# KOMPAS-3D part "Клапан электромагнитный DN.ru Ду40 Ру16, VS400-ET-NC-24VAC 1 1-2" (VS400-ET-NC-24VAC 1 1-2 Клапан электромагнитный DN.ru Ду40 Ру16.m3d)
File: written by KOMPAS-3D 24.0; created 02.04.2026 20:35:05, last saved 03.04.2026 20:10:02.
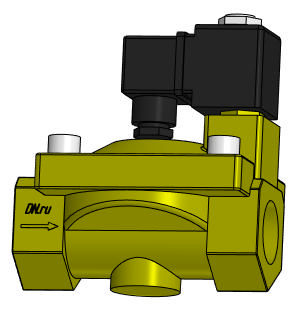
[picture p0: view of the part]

Document properties: Автор: artio; Полное имя файла: C:\Users\artio\OneDrive\Рабочий стол\Клапан электромагнитный DN.ru\VS400-ET-NC\VS400-ET-NC-24VAC 1 1-2 Клапан электромагнитный DN.ru Ду40 Ру16.m3d

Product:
- Body: Тело 1  | qty 1
    Масса: 4.144257
- Part/product: Клапан электромагнитный DN.ru Ду40 Ру16  | designation VS400-ET-NC-24VAC 1 1-2
    Масса: 2.321
    Раздел спецификации: Прочие изделия
    Примечание: D130-05491
    additional columns: ef56311e-7521-43dc-8291-0e6108b3d81d; VS400-ET-NC-220VAC 1 1-2; artio; c; Шероховатость не задана; Да

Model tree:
1. Операция без истории:1

Expressions: VS400-ET-NC-24VAC 1 1-2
